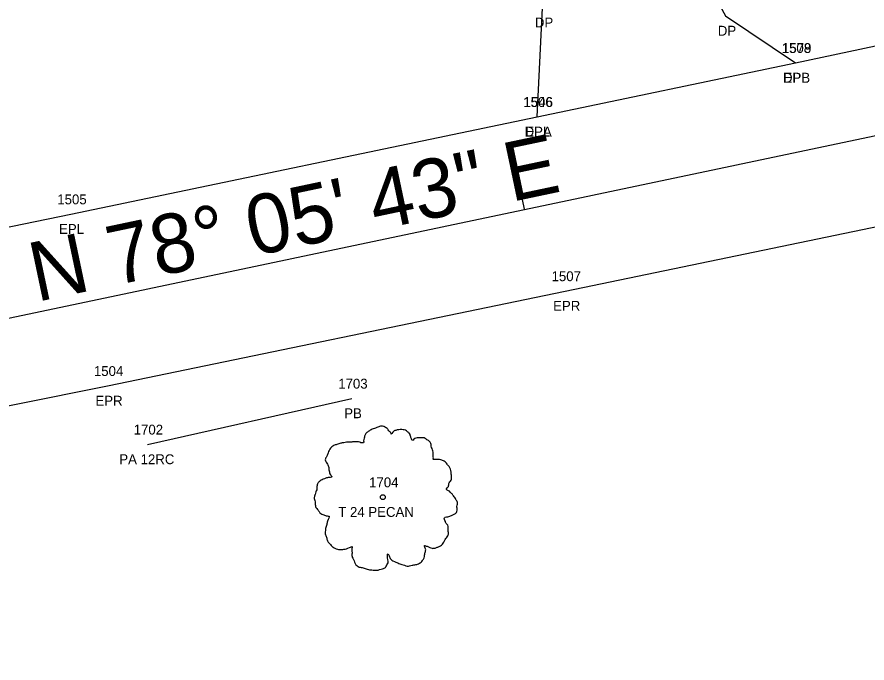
# Model space of a CAD drawing. Extents: x 1964982 to 1970452, y 1116335 to 1119906.
# Drawn here: x 1966525.7 to 1966611.8, y 1117353.3 to 1117418.7 of the extents above; entities that cross this region are included whole.
import ezdxf

# ---------------------------------------------------------------- set-up
doc = ezdxf.new("R2010")
doc.units = 0
for name, color, linetype in [('RD_EX_DR_Pipe', 7, 'Continuous'), ('RD_EX_DR_Pipe_txCode', 7, 'Continuous'), ('RD_EX_Driveway', 7, 'Continuous'), ('RD_EX_Driveway_txCode', 7, 'Continuous'), ('RD_EX_DV_Prop', 7, 'Continuous'), ('RD_EX_Road', 7, 'Continuous'), ('RD_EX_Road_txCode', 7, 'Continuous'), ('RD_EX_RW', 7, 'Continuous'), ('RD_EX_VEG', 7, 'Continuous'), ('RD_EX_VEG_txCode', 7, 'Continuous'), ('RD_HC_CL', 7, 'Continuous'), ('RD_HC_Data', 7, 'Continuous'), ('RD_HC_Data_Tic', 7, 'Continuous'), ('RD_SMD_Locator', 7, 'Continuous')]:
    doc.layers.add(name, color=color, linetype=linetype)

msp = doc.modelspace()

# ---------------------------------------------------------------- linework, layer by layer
at = {"layer": 'RD_EX_DR_Pipe'}
msp.add_line((1966538.934, 1117375.409), (1966559.639, 1117380.064), dxfattribs=at)
at = {"layer": 'RD_EX_Driveway'}
msp.add_lwpolyline([(1966578.388, 1117408.593), (1966578.939, 1117419.648), (1966578.028, 1117435.239), (1966589.341, 1117436.481), (1966594.391, 1117424.44), (1966597.459, 1117418.815), (1966604.527, 1117414.058)], dxfattribs=at)
at = {"layer": 'RD_EX_DV_Prop'}
msp.add_line((1966425.261, 1117367.215), (1966684.872, 1117421.945), dxfattribs=at)
at = {"layer": 'RD_EX_Road'}
for points in [[(1966484.547, 1117389.131), (1966531.199, 1117398.733), (1966578.388, 1117408.593), (1966604.527, 1117414.058), (1966624.537, 1117418.323), (1966671.319, 1117428.348), (1966716.506, 1117439.32), (1966736.604, 1117445.59), (1966754.133, 1117451.442), (1966759.658, 1117453.517), (1966769.512, 1117457.475)], [(1965729.992, 1117080.297), (1965819.77, 1117119.134), (1965907.737, 1117159.312), (1965995.365, 1117199.039), (1966039.268, 1117218.497), (1966081.241, 1117237.148), (1966124.665, 1117256.555), (1966167.659, 1117275.555), (1966211.467, 1117293.627), (1966257.791, 1117311.581), (1966302.7, 1117327.207), (1966347.903, 1117339.982), (1966394.806, 1117351.637), (1966441.557, 1117361.865), (1966488.625, 1117372.057), (1966534.906, 1117381.34), (1966581.234, 1117390.947), (1966629.533, 1117400.947), (1966675.632, 1117411.107), (1966721.676, 1117422.847), (1966766.802, 1117438.972), (1966775.751, 1117440.571)]]:
    msp.add_lwpolyline(points, dxfattribs=at)
at = {"layer": 'RD_EX_RW'}
for points in [[(1966484.547, 1117389.131), (1966531.199, 1117398.733), (1966578.388, 1117408.593), (1966604.527, 1117414.058), (1966624.537, 1117418.323), (1966671.319, 1117428.348), (1966716.506, 1117439.32), (1966736.604, 1117445.59), (1966754.133, 1117451.442), (1966759.658, 1117453.517), (1966769.512, 1117457.475)], [(1965729.992, 1117080.297), (1965819.77, 1117119.134), (1965907.737, 1117159.312), (1965995.365, 1117199.039), (1966039.268, 1117218.497), (1966081.241, 1117237.148), (1966124.665, 1117256.555), (1966167.659, 1117275.555), (1966211.467, 1117293.627), (1966257.791, 1117311.581), (1966302.7, 1117327.207), (1966347.903, 1117339.982), (1966394.806, 1117351.637), (1966441.557, 1117361.865), (1966488.625, 1117372.057), (1966534.906, 1117381.34), (1966581.234, 1117390.947), (1966629.533, 1117400.947), (1966675.632, 1117411.107), (1966721.676, 1117422.847), (1966766.802, 1117438.972), (1966775.751, 1117440.571)]]:
    msp.add_lwpolyline(points, dxfattribs=at)
at = {"layer": 'RD_EX_VEG'}
for centre, radius in [((1966562.766, 1117370.068), 0.25), ((1966562.753, 1117370.05), 0.0001)]:
    msp.add_circle(centre, radius, dxfattribs=at)
for points in [[(1966562.897, 1117377.236), (1966562.598, 1117377.261), (1966562.273, 1117377.161), (1966562.023, 1117377.061), (1966561.798, 1117376.986), (1966561.573, 1117376.886), (1966561.273, 1117376.711), (1966561.048, 1117376.511), (1966560.923, 1117376.261), (1966560.873, 1117376.036), (1966560.823, 1117375.761), (1966560.823, 1117375.586), (1966560.698, 1117375.561), (1966560.548, 1117375.586), (1966560.299, 1117375.661), (1966560.049, 1117375.661), (1966559.799, 1117375.661), (1966559.449, 1117375.636), (1966559.099, 1117375.636), (1966558.824, 1117375.586), (1966558.499, 1117375.536), (1966558.125, 1117375.411), (1966557.775, 1117375.286), (1966557.475, 1117375.037), (1966557.225, 1117374.562), (1966557.1, 1117374.212), (1966556.95, 1117373.962), (1966557.1, 1117373.512), (1966557.275, 1117373.162), (1966557.3, 1117372.962), (1966557.375, 1117372.538), (1966557.475, 1117372.313), (1966557.6, 1117372.113), (1966557.525, 1117372.088), (1966557.15, 1117372.038), (1966556.85, 1117371.938), (1966556.425, 1117371.713), (1966556.2, 1117371.488), (1966556.1, 1117371.163), (1966556.075, 1117370.813), (1966555.976, 1117370.614), (1966555.901, 1117370.339), (1966555.876, 1117370.264), (1966555.826, 1117369.939), (1966555.926, 1117369.489), (1966555.951, 1117369.139), (1966556.075, 1117368.914), (1966556.225, 1117368.739), (1966556.4, 1117368.489), (1966556.8, 1117368.265), (1966557.125, 1117368.165), (1966557.325, 1117368.14), (1966557.15, 1117367.64), (1966557.1, 1117367.29), (1966556.975, 1117366.89), (1966556.975, 1117366.815), (1966556.925, 1117366.34), (1966557.075, 1117366.015), (1966557.15, 1117365.641), (1966557.325, 1117365.416), (1966557.6, 1117365.116), (1966557.925, 1117364.891), (1966558.424, 1117364.766), (1966558.824, 1117364.791), (1966559.399, 1117364.966), (1966559.649, 1117365.041), (1966559.624, 1117364.866), (1966559.649, 1117364.491), (1966559.649, 1117364.066), (1966559.799, 1117363.742), (1966559.899, 1117363.467), (1966560.049, 1117363.217), (1966560.374, 1117362.992), (1966560.773, 1117362.917), (1966561.198, 1117362.767), (1966561.648, 1117362.692), (1966562.148, 1117362.667), (1966562.748, 1117362.817), (1966563.022, 1117362.942), (1966563.122, 1117363.117), (1966563.322, 1117363.492), (1966563.272, 1117363.717), (1966563.297, 1117364.316), (1966563.397, 1117364.141), (1966563.572, 1117363.791), (1966564.072, 1117363.492), (1966564.472, 1117363.317), (1966564.947, 1117363.167), (1966565.246, 1117363.092), (1966565.721, 1117363.167), (1966566.096, 1117363.242), (1966566.471, 1117363.367), (1966566.771, 1117363.642), (1966566.946, 1117363.916), (1966566.996, 1117364.191), (1966567.071, 1117364.566), (1966567.121, 1117364.741)], [(1966567.121, 1117364.741), (1966567.046, 1117364.916), (1966566.996, 1117365.166), (1966567.071, 1117365.141), (1966567.246, 1117365.091), (1966567.52, 1117364.966), (1966567.745, 1117364.891), (1966568.07, 1117364.916), (1966568.345, 1117365.016), (1966568.795, 1117365.291), (1966569.07, 1117365.766), (1966569.345, 1117366.165), (1966569.42, 1117366.49), (1966569.37, 1117366.715), (1966569.345, 1117367.215), (1966569.145, 1117367.465), (1966569.095, 1117367.59), (1966568.995, 1117367.99), (1966569.07, 1117368.04), (1966569.345, 1117368.09), (1966569.719, 1117368.215), (1966569.994, 1117368.339), (1966570.219, 1117368.514), (1966570.294, 1117368.739), (1966570.269, 1117369.139), (1966570.319, 1117369.539), (1966570.244, 1117369.689), (1966570.144, 1117369.839), (1966570.069, 1117370.039), (1966569.919, 1117370.189), (1966569.819, 1117370.339), (1966569.719, 1117370.439), (1966569.595, 1117370.589), (1966569.42, 1117370.713), (1966569.27, 1117370.763), (1966569.22, 1117370.913), (1966569.37, 1117371.113), (1966569.42, 1117371.213), (1966569.445, 1117371.438), (1966569.67, 1117371.788), (1966569.719, 1117372.188), (1966569.67, 1117372.613), (1966569.62, 1117372.888), (1966569.47, 1117373.162), (1966569.27, 1117373.412), (1966569.145, 1117373.587), (1966568.97, 1117373.712), (1966568.645, 1117373.837), (1966568.395, 1117373.887), (1966568.045, 1117373.887), (1966567.845, 1117373.937), (1966567.87, 1117373.987), (1966567.87, 1117374.137), (1966567.87, 1117374.412), (1966567.795, 1117374.862), (1966567.645, 1117375.361), (1966567.645, 1117375.386), (1966567.545, 1117375.636), (1966567.321, 1117375.836), (1966567.146, 1117375.936), (1966566.946, 1117376.061), (1966566.696, 1117376.086), (1966566.396, 1117376.086), (1966566.121, 1117376.036), (1966565.921, 1117375.936), (1966565.746, 1117375.811), (1966565.671, 1117375.961), (1966565.571, 1117376.261), (1966565.521, 1117376.411), (1966565.371, 1117376.586), (1966565.147, 1117376.786), (1966564.697, 1117376.911), (1966564.072, 1117376.836), (1966563.772, 1117376.636), (1966563.622, 1117376.461), (1966563.572, 1117376.586), (1966563.372, 1117376.786), (1966563.272, 1117376.961), (1966563.097, 1117377.086), (1966562.947, 1117377.186), (1966562.847, 1117377.236)]]:
    msp.add_spline(points, degree=3, dxfattribs=at)
at = {"layer": 'RD_HC_CL'}
msp.add_line((1966425.261, 1117367.215), (1966684.871, 1117421.945), dxfattribs=at)
at = {"layer": 'RD_HC_Data_Tic'}
msp.add_line((1966577.124, 1117399.23), (1966576.299, 1117403.144), dxfattribs=at)
at = {"layer": 'RD_SMD_Locator'}
for centre in [(1966604.527, 1117414.058), (1966604.527, 1117414.058), (1966604.527, 1117414.058), (1966604.527, 1117414.058), (1966578.388, 1117408.593), (1966578.388, 1117408.593), (1966578.388, 1117408.593), (1966578.388, 1117408.593), (1966531.199, 1117398.733), (1966531.199, 1117398.733), (1966581.234, 1117390.947), (1966581.234, 1117390.947), (1966534.906, 1117381.34), (1966534.906, 1117381.34), (1966559.639, 1117380.064), (1966538.934, 1117375.409)]:
    msp.add_circle(centre, 0.001, dxfattribs=at)

# ---------------------------------------------------------------- texts
at = {"layer": 'RD_EX_DR_Pipe_txCode'}
for s, p in [('1703', (1966558.253, 1117381.064)), ('PB', (1966558.859, 1117378.064)), ('1702', (1966537.548, 1117376.409)), ('PA 12RC', (1966536.092, 1117373.409))]:
    msp.add_text(s, height=1, dxfattribs=at).set_placement(p)
at = {"layer": 'RD_EX_Driveway_txCode'}
for s, p in [('DP', (1966578.159, 1117417.648)), ('DP', (1966578.159, 1117417.648)), ('DP', (1966596.679, 1117416.815)), ('DP', (1966596.679, 1117416.815)), ('1579', (1966603.181, 1117415.058)), ('1579', (1966603.181, 1117415.058)), ('DPB', (1966603.275, 1117412.058)), ('DPB', (1966603.275, 1117412.058)), ('1546', (1966577.018, 1117409.593)), ('1546', (1966577.018, 1117409.593)), ('DPA', (1966577.12, 1117406.593)), ('DPA', (1966577.12, 1117406.593))]:
    msp.add_text(s, height=1, dxfattribs=at).set_placement(p)
at = {"layer": 'RD_EX_Road_txCode'}
for s, p in [('1508', (1966603.141, 1117415.058)), ('1508', (1966603.141, 1117415.058)), ('EPL', (1966603.322, 1117412.058)), ('EPL', (1966603.322, 1117412.058)), ('1506', (1966576.978, 1117409.593)), ('1506', (1966576.978, 1117409.593)), ('EPL', (1966577.183, 1117406.593)), ('EPL', (1966577.183, 1117406.593)), ('1505', (1966529.813, 1117399.733)), ('1505', (1966529.813, 1117399.733)), ('EPL', (1966529.994, 1117396.733)), ('EPL', (1966529.994, 1117396.733)), ('1507', (1966579.848, 1117391.947)), ('1507', (1966579.848, 1117391.947)), ('EPR', (1966580.006, 1117388.947)), ('EPR', (1966580.006, 1117388.947)), ('1504', (1966533.52, 1117382.34)), ('1504', (1966533.52, 1117382.34)), ('EPR', (1966533.677, 1117379.34)), ('EPR', (1966533.677, 1117379.34))]:
    msp.add_text(s, height=1, dxfattribs=at).set_placement(p)
at = {"layer": 'RD_EX_VEG_txCode'}
for s, p in [('1704', (1966561.38, 1117371.068)), ('T 24 PECAN', (1966558.254, 1117368.068))]:
    msp.add_text(s, height=1, dxfattribs=at).set_placement(p)
at = {"layer": 'RD_HC_Data'}
msp.add_text('N 78° 05\' 43" E', height=6, rotation=11.90472, dxfattribs=at).set_placement((1966527.716, 1117389.836))

doc.saveas('drawing.dxf')
